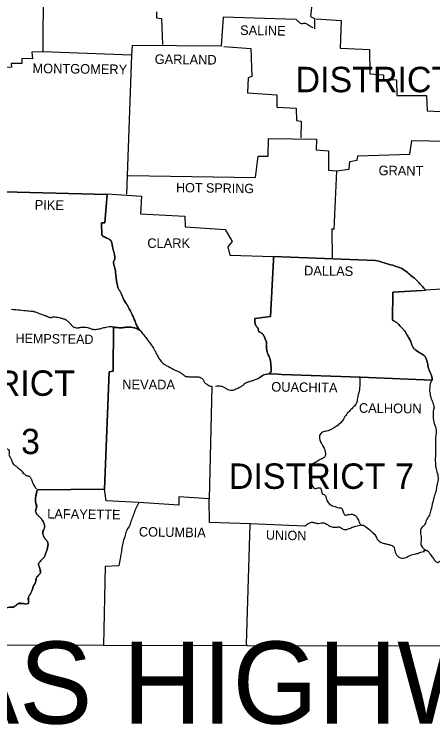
# Model space of a CAD drawing. Extents: x -43543 to 34500, y -13675 to 11152.
# Drawn here: x 11720 to 13557, y 4715 to 7833 of the extents above; entities that cross this region are included whole.
import ezdxf

# ---------------------------------------------------------------- set-up
doc = ezdxf.new("R2010")
doc.units = 0
for name, color, linetype in [('1', 7, 'Continuous'), ('2', 7, 'Continuous'), ('3', 7, 'Continuous'), ('R_Annotation', 7, 'Continuous')]:
    doc.layers.add(name, color=color, linetype=linetype)

msp = doc.modelspace()

# ---------------------------------------------------------------- linework, layer by layer
at = {"layer": '1'}
for points in [[(12379.4, 8503.9), (12375.5, 8363), (12152.5, 8362), (12123.1, 8336.6), (12106.5, 8297.5), (12082, 8299.4), (12081, 8276.9), (12052.7, 8274), (12053.6, 8253.4), (11911.8, 8257.3), (11906.9, 8241.7), (11848.2, 8239.7), (11846.2, 7667.4), (11797.3, 7666.4), (11801.2, 7637), (11754.2, 7638), (11753.3, 7616.5), (11707.3, 7616.5), (11708.3, 7600.8), (11639.8, 7598.9), (11638.8, 7539.2), (11572.3, 7545.1), (11561.5, 7063.7)], [(13347.1, 7958.9), (13276.6, 7966.8), (13279.6, 7940.3), (13151.4, 7935.4), (13147.5, 7897.3), (13027.1, 7890.4), (13020.3, 7822), (13037.9, 7813.1), (13037.9, 7768.1)], [(12345.2, 7843.5), (12344.2, 7817.1), (12366.7, 7813.1), (12370.6, 7699.6)], [(12957.7, 7809.2), (12637.7, 7819), (12628.9, 7692.8), (12237.6, 7694.8), (12235.6, 7652.7)], [(13044.8, 7812.2), (13154.3, 7805.3), (13150.4, 7683), (13278.6, 7678.1), (13280.6, 7571.5), (13341.2, 7566.6), (13341.2, 7548), (13398, 7544.1), (13399.9, 7475.6), (13529.1, 7475.6), (13533, 7408.1), (13652.3, 7402.2), (13651.4, 7275)], [(12640.7, 7690.8), (12759.1, 7682), (12763, 7558.8), (12746.3, 7552.9), (12744.4, 7487.3), (12872.6, 7478.5), (12872.6, 7424.7), (12957.7, 7419.8), (12958.7, 7366), (12979.2, 7363.1), (12978.2, 7290.7)], [(12235.6, 7652.7), (11846.2, 7667.4)], [(12235.6, 7652.7), (12213.1, 7043.1)], [(12220, 7124.3), (12779.6, 7116.5), (12790.4, 7209.5), (12834.4, 7209.5), (12835.4, 7287.7), (13046.7, 7284.8), (13044.8, 7237.8), (13099.5, 7233.9), (13099.5, 7147.8), (13134.8, 7144.9)], [(13134.8, 7144.9), (13189.6, 7152.7), (13193.5, 7186), (13225.8, 7191.9), (13227.7, 7211.4), (13455.7, 7218.3), (13464.5, 7278), (13698.3, 7274)], [(13134.8, 7144.9), (13123, 6888.6), (13114.2, 6891.5), (13115.2, 6758.4)], [(12127.8, 7042.1), (12128, 7044.1)], [(12128, 7044.1), (12278.7, 7034.3), (12274.8, 6957), (12469.5, 6946.3), (12470.4, 6899.3), (12646.5, 6888.6), (12676.9, 6835.7), (12658.3, 6812.2), (12667.1, 6776), (12858.7, 6769)], [(13667, 6630.3), (13524.2, 6621.4)], [(12587.8, 6199.8), (12575.1, 5706.6)], [(12264.5, 5690.1), (12124.1, 5697.8), (12117.2, 5748.7)], [(12994.9, 5587.3), (12755, 5596.3)], [(11681.9, 5065.4), (12112.4, 5064.6)], [(12742, 5063.6), (15008.4, 5059.9)]]:
    msp.add_lwpolyline(points, dxfattribs=at)
for points in [[(13031.1, 7773), (13012.5, 7782.8), (12997.8, 7791.6), (12982.1, 7790.6), (12969.4, 7798.5), (12957.7, 7809.2)], [(11708.3, 6538.3), (11745.4, 6535.3), (11779.7, 6531.4), (11792.9, 6530.4), (11799.5, 6529.7), (11802.8, 6529.2), (11806.1, 6528.5), (11813.1, 6526.5), (11819.9, 6524), (11833.5, 6518.7), (11858, 6509.9), (11861.9, 6508.3), (11865.7, 6506.4), (11869.6, 6504.6), (11873.6, 6503.1), (11880.1, 6502.4), (11886.7, 6503.5), (11893.4, 6504.9), (11900, 6505), (11911.3, 6502.9), (11922.5, 6500.1), (11935.6, 6496.6), (11941.9, 6494.4), (11945, 6493), (11948, 6491.3), (11957.8, 6483.5), (11966.6, 6474.7), (11969.4, 6471.5), (11972, 6468.2), (11976.4, 6463.4), (11977.3, 6462.7), (11978.3, 6462), (11983.8, 6459), (11989.4, 6457.5), (11995.1, 6457), (12000.8, 6457.1), (12005.4, 6457.6), (12010.1, 6458.6), (12014.7, 6459.6), (12019.4, 6460), (12041.9, 6458.1), (12048.3, 6456.3), (12054.6, 6453.9), (12060.9, 6451.6), (12067.3, 6450.2), (12072.4, 6449.8), (12077.6, 6449.9), (12087.9, 6451.2), (12104.5, 6455.1), (12124.1, 6460), (12136.3, 6461.9), (12142.4, 6462.1), (12148.5, 6462), (12153.2, 6461.3), (12157.9, 6460.1)], [(12271.9, 6445.9), (12278.7, 6437.5), (12308, 6400.3), (12321.7, 6381.6), (12328.1, 6371.9), (12334.4, 6362.2), (12338.4, 6355.3), (12341.9, 6348.1), (12345.4, 6340.9), (12349.1, 6333.8), (12358.9, 6317.1), (12364.7, 6309.4), (12368, 6305.8), (12371.6, 6302.5), (12384, 6293.9), (12397.1, 6286.8), (12429.3, 6270.2), (12449.9, 6260.4), (12455.8, 6256.3), (12461.3, 6251.3), (12466.9, 6246.7), (12470, 6244.9), (12473.4, 6243.8), (12488.5, 6242.1), (12503.7, 6241.8), (12515, 6241.9), (12520.6, 6241.9), (12526.2, 6241.8), (12531.7, 6241), (12536.9, 6239.1), (12542, 6236.4), (12546.7, 6233), (12549.9, 6229), (12551.9, 6224.2), (12553.7, 6219.4), (12556.5, 6215.4), (12560.6, 6212), (12564.8, 6208.9), (12574.1, 6203.7), (12587.8, 6199.8)], [(12815.8, 6250.6), (12790.4, 6234), (12770.8, 6226.2), (12756.1, 6221.3), (12742.4, 6217.4), (12724.8, 6205.6), (12711.1, 6195.8), (12692.5, 6187), (12674.9, 6181.2), (12653.4, 6188), (12641.7, 6194.9), (12628.9, 6199.8), (12602.9, 6199.8)], [(12790.4, 6234), (12815.8, 6250.6), (12834.4, 6254.5)], [(13236, 6240), (13233.6, 6179.2), (13226.7, 6148.9), (13219.9, 6121.5), (13205.2, 6105.8), (13189.6, 6090.2), (13174.9, 6072.6), (13162.2, 6051), (13149.4, 6037.3), (13132.8, 6023.6), (13116.2, 6013.9), (13097.6, 6005), (13077, 6000.2), (13062.4, 5989.4), (13061.4, 5965.9), (13078, 5932.6), (13083.9, 5917), (13085.9, 5898.4), (13079, 5887.6), (13063.3, 5878.8), (13044.8, 5868.1), (13028.1, 5858.3), (13016.4, 5841.7), (13014.4, 5819.2), (13022.3, 5792.7), (13025.2, 5777.1), (13037.9, 5752.6), (13047.7, 5753.6), (13065.3, 5752.6), (13067.3, 5747.7), (13068.2, 5742.8), (13072.2, 5730.1), (13086.8, 5719.4), (13088.8, 5709.6), (13097.6, 5691), (13112.3, 5678.3), (13123, 5674.3), (13145.5, 5667.5), (13157.3, 5664.6), (13170, 5636.2), (13185.6, 5637.2), (13197.4, 5639.1), (13217, 5634.2), (13225.8, 5622.5), (13234.6, 5602.9), (13244.5, 5590.4), (13251, 5591.2)], [(13553.5, 6227.3), (13551.5, 6223.6), (13549.1, 6220), (13547, 6216.3), (13545.7, 6212.5), (13545, 6207.7), (13544.3, 6202.8), (13543.3, 6193), (13543, 6183.1), (13543.7, 6173.3), (13546.1, 6160), (13549.6, 6146.9), (13551.4, 6142), (13553.5, 6137.1), (13555.5, 6132.3), (13557.4, 6127.3), (13559.3, 6121.8), (13560.8, 6116.2), (13561.8, 6110.5), (13562.2, 6107.6), (13562.3, 6104.8), (13561.6, 6101.3), (13560.6, 6099.6), (13559.4, 6098)], [(13559.4, 6098), (13563.3, 6037.3), (13572.1, 6008), (13569.2, 5976.7), (13568.2, 5946.3), (13568.2, 5918.9), (13568.2, 5892.5), (13568.2, 5865.1), (13570.2, 5845.6), (13577, 5817.2), (13579.9, 5790.8), (13574.1, 5765.3), (13571.1, 5741.9), (13563.3, 5718.4), (13556.5, 5692), (13548.6, 5657.7), (13541.8, 5635.2), (13528.1, 5611.7), (13519.3, 5590.2), (13505.6, 5576.5), (13503.6, 5553), (13506.6, 5531.5), (13504.6, 5511.9), (13511.5, 5493.3), (13529.1, 5480.6)], [(11663.2, 5926.8), (11666.4, 5928), (11669.6, 5930.3), (11672.8, 5932.2), (11676, 5932.6), (11681.3, 5930.7), (11686.7, 5927.8), (11692, 5924.8), (11694.3, 5923), (11695.5, 5922), (11696.5, 5920.9), (11698.7, 5915.1), (11698.2, 5908.4), (11697.3, 5901.6), (11698.5, 5895.5), (11700.4, 5892), (11702.4, 5888.6), (11704.4, 5885.2), (11706.3, 5881.8), (11709, 5875.5), (11711.3, 5869), (11715.9, 5859.9), (11716.9, 5858.6), (11718, 5857.3), (11722, 5853.8), (11726.2, 5850.7), (11730.5, 5847.7), (11734.7, 5844.6), (11742.6, 5838.3), (11750.3, 5831.9), (11752, 5830.1), (11753.4, 5828.1), (11754.7, 5826), (11756.2, 5824), (11764.1, 5816.2), (11768.4, 5812.7), (11772.8, 5809.4), (11776.4, 5807.9), (11780.3, 5807.2), (11784.2, 5806.4), (11786, 5805.7), (11787.5, 5804.5), (11791.4, 5799.4), (11794.4, 5793.7), (11797.1, 5787.4), (11799.7, 5781), (11802.3, 5774.6), (11805.1, 5768.3), (11810.2, 5759.2), (11813.4, 5755), (11815.2, 5752.9), (11817.3, 5750.8)], [(12994.9, 5587.3), (13010.5, 5598), (13025.2, 5603.9), (13039.9, 5601), (13055.5, 5599), (13069.2, 5601), (13086.8, 5598), (13101.5, 5589.2), (13118.1, 5582.4), (13134.8, 5582.4), (13149.4, 5582.4), (13162.2, 5573.6), (13185.6, 5574.5), (13205.2, 5582.4), (13224.8, 5588.2), (13251.2, 5591.2), (13274.7, 5574.5), (13291.3, 5560.9), (13305, 5545.2), (13314.8, 5527.6), (13325.6, 5517.8), (13343.2, 5511), (13356.9, 5508), (13373.5, 5503.1), (13382.3, 5499.2), (13390.1, 5480.6), (13402.9, 5455.2), (13427.3, 5446.4), (13457.6, 5458.1), (13482.1, 5465), (13499.7, 5470.8), (13510.5, 5474.8), (13520.3, 5475.7), (13517.3, 5477.7), (13529.1, 5480.6), (13539.8, 5472.8), (13546.7, 5462), (13558.4, 5446.4), (13569.2, 5432.7), (13579.9, 5427.8), (13590.7, 5433.7), (13605.4, 5428.8), (13618.1, 5423.9), (13632.8, 5420), (13645.5, 5419), (13662.1, 5415.1), (13674.9, 5408.2), (13686.6, 5401.4), (13698.3, 5388.7), (13710.1, 5369.1), (13714, 5353.4), (13727.7, 5337.8), (13740.4, 5337.8), (13759, 5312.3), (13765.8, 5302.6), (13780.5, 5284.9), (13791.3, 5284.9), (13808.2, 5281.7)]]:
    msp.add_spline(points, degree=3, dxfattribs=at)
at = {"layer": 'R_Annotation'}
for p, q in [((13305, 6752.6), (12858.7, 6769)), ((12270.7, 6445.9), (12271.9, 6445.9))]:
    msp.add_line(p, q, dxfattribs=at)
for points in [[(11561.5, 7056.9), (12127.8, 7042), (12127.8, 7042.1), (12118.2, 6917.9), (12102.6, 6916.9), (12104.5, 6863.1)], [(12104.5, 6863.1), (12102.6, 6916.9), (12118.2, 6917.9), (12127.8, 7042), (11561.5, 7056.9)], [(12776.7, 6498.2), (12844.2, 6506), (12858.7, 6754.1), (12858.7, 6769)], [(12858.7, 6769), (12858.7, 6754.1), (12844.2, 6506), (12776.7, 6498.2)], [(12858.7, 6769), (13305, 6752.6)], [(13380.4, 6490.3), (13381.3, 6612.6), (13508.7, 6620.5), (13525.8, 6621.5)], [(13508.7, 6620.5), (13381.3, 6612.6), (13380.4, 6490.3)], [(12156.4, 6460.4), (12154.4, 6266.3), (12136.8, 6264.3), (12117.2, 5748.7), (11820.8, 5745.8)], [(11820.8, 5745.8), (12117.2, 5748.7), (12136.8, 6264.3), (12154.4, 6266.3), (12156.4, 6460.4)], [(12270.7, 6445.9), (12271.4, 6446.5)], [(13553.5, 6227.6), (13239.5, 6239.9), (12893.3, 6252.4), (12880.5, 6252.9), (12834.4, 6254.5)], [(12839.1, 6254.4), (12880.5, 6252.9), (12893.3, 6252.4), (13239.5, 6239.9), (13553.5, 6227.3)], [(12755, 5596.3), (12577.1, 5602.9), (12575.1, 5701.7), (12575.1, 5706.6), (12443, 5715.4), (12442.1, 5679.2), (12267.7, 5689.9)], [(12755, 5596.3), (12577.1, 5602.9), (12575.1, 5701.7), (12575.1, 5706.6), (12443, 5715.4), (12442.1, 5679.2), (12267.8, 5689.9)], [(12179.8, 5413.1), (12119.2, 5409.2), (12112.3, 5064.6), (12112.4, 5064.6), (12742, 5063.6), (12739.9, 5069.7), (12755.1, 5594.1), (12755, 5596.3)], [(12179.8, 5413.1), (12119.2, 5409.2), (12112.3, 5064.6), (12742, 5063.6), (12739.9, 5069.7), (12755.1, 5594.1), (12755, 5596.3)]]:
    msp.add_lwpolyline(points, dxfattribs=at)
for points in [[(12104.5, 6863.1), (12120.2, 6853.3), (12124.7, 6851), (12129.4, 6849.1), (12134.2, 6847.1), (12138.8, 6844.5), (12145, 6838), (12148.5, 6829.8), (12149.7, 6824.2), (12150.5, 6818.6), (12151.4, 6812.9), (12152.5, 6807.3), (12154.1, 6801.2), (12155.9, 6795.1), (12157.7, 6789), (12159.3, 6782.9), (12160.5, 6776.6), (12161.1, 6770.1), (12161.4, 6763.7), (12161.3, 6757.4), (12160.2, 6753.9), (12158, 6750.6), (12156, 6747.2), (12155.4, 6743.7), (12157, 6736), (12159.2, 6728.2), (12161.6, 6720.4), (12163.2, 6712.4), (12166.1, 6690.9), (12169.1, 6665.5), (12172, 6648.1), (12174.1, 6639.6), (12176.9, 6631.2), (12179.7, 6625.1), (12183.1, 6619.3), (12186.5, 6613.6), (12189.6, 6607.7), (12192.6, 6600.7), (12195.3, 6593.5), (12198.1, 6586.3), (12201.4, 6579.4), (12206, 6571.6), (12211.1, 6564.2), (12216.3, 6556.8), (12220.9, 6549), (12237.6, 6515.8), (12245.4, 6498.2), (12248.9, 6489), (12252.1, 6479.8), (12255.6, 6470.7), (12260.1, 6462), (12265.8, 6453.7), (12271.9, 6445.9)], [(12170.5, 6656.2), (12169.1, 6665.5), (12166.1, 6690.9), (12163.2, 6712.4), (12161.6, 6720.4), (12159.2, 6728.2), (12157, 6736), (12155.4, 6743.7), (12156, 6747.2), (12158, 6750.6), (12160.2, 6753.9), (12161.3, 6757.4), (12161.4, 6763.7), (12161.1, 6770.1), (12160.5, 6776.6), (12159.3, 6782.9), (12157.7, 6789), (12155.9, 6795.1), (12154.1, 6801.2), (12152.5, 6807.3), (12151.4, 6812.9), (12150.5, 6818.6), (12149.7, 6824.2), (12148.5, 6829.8), (12145, 6838), (12138.8, 6844.5), (12134.2, 6847.1), (12129.4, 6849.1), (12124.7, 6851), (12120.2, 6853.3), (12104.5, 6863.1)], [(13305, 6752.6), (13381.3, 6731), (13420.5, 6716.4), (13459.6, 6688), (13491.9, 6659.6), (13525.8, 6621.5)], [(13525.8, 6621.5), (13491.9, 6659.6), (13459.6, 6688), (13420.5, 6716.4), (13381.3, 6731), (13305, 6752.6)], [(12271.4, 6446.5), (12265.8, 6453.7), (12260.1, 6462), (12255.6, 6470.7), (12252.1, 6479.8), (12248.9, 6489), (12245.4, 6498.2), (12237.6, 6515.8), (12220.9, 6549), (12216.3, 6556.8), (12211.1, 6564.2), (12206, 6571.6), (12201.4, 6579.4), (12198.1, 6586.3), (12195.3, 6593.5), (12192.6, 6600.7), (12189.6, 6607.7), (12186.5, 6613.6), (12183.1, 6619.3), (12179.7, 6625.1), (12176.9, 6631.2), (12174.1, 6639.6), (12172, 6648.1), (12170.5, 6656.2)], [(12776.7, 6498.2), (12776.7, 6479.6), (12779.4, 6470.6), (12781.3, 6466.2), (12783.5, 6462), (12785.1, 6459.8), (12786.9, 6458), (12788.8, 6456.1), (12790.4, 6454.1), (12791.3, 6451.1), (12791.5, 6447.6), (12791.8, 6444.2), (12793.3, 6441.4), (12794.3, 6440.5), (12795.4, 6439.8), (12797.6, 6438.4), (12799.9, 6437.1), (12802.1, 6435.5), (12803.8, 6434.2), (12805.6, 6432.9), (12809.1, 6430.3), (12814.8, 6423.8), (12821.7, 6407.2), (12822.9, 6404.5), (12824.3, 6401.9), (12825.6, 6399.2), (12826.6, 6396.4), (12826.8, 6395.6), (12826.9, 6394.7), (12826.9, 6389.6), (12826.6, 6386.1), (12826.6, 6382.7), (12827.6, 6369), (12828.3, 6360.7), (12829.5, 6352.4), (12830.5, 6348.6), (12831.8, 6344.8), (12835.1, 6337.6), (12838.5, 6330.4), (12841.2, 6323), (12844.2, 6311.3), (12846.1, 6301.5), (12846.8, 6293.2), (12847.1, 6284.9), (12847.3, 6280), (12847.4, 6275.1), (12847.3, 6270.2), (12847.1, 6265.3), (12846.3, 6262.5), (12844.3, 6259.5), (12839.1, 6254.4)], [(12834.4, 6254.5), (12847.1, 6265.3), (12847.1, 6284.9), (12846.1, 6301.5), (12844.2, 6311.3), (12841.2, 6323), (12829.5, 6352.4), (12827.6, 6369), (12826.6, 6382.7), (12826.6, 6396.4), (12821.7, 6407.2), (12814.8, 6423.8), (12802.1, 6435.5), (12793.3, 6441.4), (12790.4, 6454.1), (12783.5, 6462), (12776.7, 6479.6), (12776.7, 6498.2)], [(13380.4, 6490.3), (13386.6, 6487.3), (13392.4, 6483.9), (13397.9, 6480.1), (13402.9, 6475.7), (13421.4, 6456.1), (13428.4, 6448.8), (13431.8, 6445.2), (13433.5, 6443.3), (13435.1, 6441.4), (13437.8, 6437.6), (13439.9, 6433.3), (13441.8, 6429), (13443.9, 6424.8), (13449.8, 6415), (13455.7, 6405.2), (13460, 6396.1), (13463.5, 6386.5), (13467.3, 6377), (13469.6, 6372.4), (13470.9, 6370.2), (13472.3, 6368), (13479.1, 6361), (13487, 6355.3), (13507.5, 6342.6), (13514, 6338.5), (13517.2, 6336.3), (13518.8, 6335.1), (13520.3, 6333.8), (13525.2, 6327.7), (13528.6, 6320.6), (13531, 6313.1), (13533, 6305.4), (13534.6, 6298.3), (13535.8, 6291.1), (13537, 6284), (13538.9, 6277), (13541.3, 6270.6), (13544.1, 6264.3), (13547, 6258), (13549.6, 6251.6), (13552.8, 6241.8), (13553.9, 6236.9), (13554.3, 6234.5), (13554.5, 6232), (13553.5, 6227.3)], [(13477.6, 6362.2), (13472.3, 6368), (13470.9, 6370.2), (13469.6, 6372.4), (13467.3, 6377), (13463.5, 6386.5), (13460, 6396.1), (13455.7, 6405.2), (13449.8, 6415), (13443.9, 6424.8), (13441.8, 6429), (13439.9, 6433.3), (13437.8, 6437.6), (13435.1, 6441.4), (13433.5, 6443.3), (13431.8, 6445.2), (13428.4, 6448.8), (13421.4, 6456.1), (13402.9, 6475.7), (13397.9, 6480.1), (13392.4, 6483.9), (13386.6, 6487.3), (13380.4, 6490.3)], [(12270.7, 6445.9), (12267.8, 6448), (12264.9, 6449.9), (12258.8, 6453.1), (12246.1, 6457.4), (12220, 6460), (12212.9, 6459.5), (12205.8, 6458.5), (12198.7, 6457.5), (12191.6, 6457.1), (12179.4, 6457.3), (12167.1, 6458.1), (12162.5, 6458.9), (12156.4, 6460.4)], [(12156.4, 6460.4), (12162.5, 6458.9), (12167.1, 6458.1), (12179.4, 6457.3), (12191.6, 6457.1), (12198.7, 6457.5), (12205.8, 6458.5), (12212.9, 6459.5), (12220, 6460), (12246.1, 6457.4), (12258.8, 6453.1), (12264.9, 6449.9), (12267.8, 6448), (12270.7, 6445.9)], [(13553.5, 6227.3), (13554.5, 6232), (13554.3, 6234.5), (13553.9, 6236.9), (13552.8, 6241.8), (13549.6, 6251.6), (13547, 6258), (13544.1, 6264.3), (13541.3, 6270.6), (13538.9, 6277), (13537, 6284), (13535.8, 6291.1), (13534.6, 6298.3), (13533, 6305.4), (13531, 6313.1), (13528.6, 6320.6), (13525.2, 6327.7), (13520.3, 6333.8), (13518.8, 6335.1), (13517.2, 6336.3), (13514, 6338.5), (13507.5, 6342.6), (13487, 6355.3), (13479.1, 6361), (13477.6, 6362.2)], [(11820.8, 5745.8), (11814.9, 5717.4), (11813.9, 5694.9), (11818.8, 5668.5), (11813.9, 5655.8), (11821.7, 5637.2), (11836.4, 5622.5), (11847.2, 5606.8), (11854, 5584.3), (11845.2, 5558.9), (11855, 5532.5), (11863.8, 5522.7), (11868.7, 5507), (11861.9, 5476.7), (11853.1, 5454.2), (11833.5, 5431.7), (11827.6, 5420.9), (11830.6, 5406.3), (11835.4, 5382.8), (11830.6, 5375.9), (11817.8, 5359.3), (11813.9, 5340.7), (11805.1, 5325.1), (11795.3, 5296.7), (11782.6, 5273.2), (11780.7, 5246.8), (11761.1, 5246.8), (11738.6, 5246.8), (11718, 5232.1), (11699.4, 5231.1), (11676.9, 5222.3), (11663.2, 5203.7), (11658.4, 5183.2), (11652.5, 5163.6), (11658.4, 5130.4), (11667.2, 5106.9), (11674, 5088.3), (11680.9, 5070.4)], [(11827.9, 5372.4), (11830.6, 5375.9), (11833.7, 5379.2), (11835.4, 5382.8), (11835.4, 5383.5), (11835.4, 5384.2), (11835.2, 5385.7), (11834.8, 5388.6), (11833.5, 5394.5), (11832, 5400.4), (11830.6, 5406.3), (11827.6, 5420.9), (11833.5, 5431.7), (11838.4, 5437.5), (11843.7, 5442.8), (11848.8, 5448.1), (11853.1, 5454.2), (11858, 5465.2), (11861.9, 5476.7), (11866.2, 5491.9), (11867.8, 5499.5), (11868.7, 5507), (11863.8, 5522.7), (11861.8, 5525.4), (11859.5, 5527.6), (11857.1, 5529.8), (11855, 5532.5), (11848.6, 5545.6), (11846.5, 5552.3), (11845.2, 5558.9), (11846.3, 5565.3), (11849.6, 5571.6), (11852.9, 5578), (11854, 5584.3), (11853.2, 5589.9), (11851.8, 5595.6), (11849.8, 5601.2), (11847.2, 5606.8), (11842.1, 5615.1), (11836.4, 5622.5), (11832.9, 5626.2), (11829.2, 5629.5), (11825.3, 5633), (11821.7, 5637.2), (11816.5, 5646.4), (11814.8, 5651.1), (11813.9, 5655.8), (11814.5, 5658.9), (11816.3, 5662.1), (11818.1, 5665.3), (11818.8, 5668.5), (11817.8, 5675), (11816.2, 5681.6), (11814.6, 5688.2), (11813.9, 5694.9), (11814.9, 5717.4), (11816, 5725.2), (11817.4, 5733.2), (11820.8, 5745.8)], [(12267.8, 5689.9), (12250.3, 5654.8), (12241.5, 5630.3), (12232.7, 5606.8), (12225.8, 5587.3), (12215.1, 5570.6), (12207.2, 5547.2), (12198.4, 5518.8), (12192.6, 5492.4), (12189.6, 5468.9), (12184.7, 5444.4), (12179.8, 5413.1)], [(12267.8, 5689.9), (12250.3, 5654.8), (12241.5, 5630.3), (12232.7, 5606.8), (12225.8, 5587.3), (12215.1, 5570.6), (12207.2, 5547.2), (12198.4, 5518.8), (12192.6, 5492.4), (12189.6, 5468.9), (12184.7, 5444.4), (12179.8, 5413.1)], [(11680.9, 5070.4), (11674, 5088.3), (11667.2, 5106.9), (11658.4, 5130.4), (11655.5, 5138.5), (11653.2, 5146.9), (11652, 5155.3), (11652.5, 5163.6), (11655.2, 5173.4), (11656.9, 5178.3), (11658.4, 5183.2), (11663.2, 5203.7), (11668.4, 5213.9), (11672.3, 5218.4), (11676.9, 5222.3), (11687.9, 5228), (11699.4, 5231.1), (11704.1, 5231.7), (11708.8, 5231.6), (11713.5, 5231.5), (11718, 5232.1), (11723.4, 5235.2), (11728.2, 5240.2), (11732.9, 5244.8), (11738.6, 5246.8), (11761.1, 5246.8), (11780.7, 5246.8), (11783.1, 5247.6), (11784.2, 5249.8), (11783.6, 5257.1), (11782, 5265.8), (11782.6, 5273.2), (11785.7, 5279), (11789.1, 5284.8), (11792.5, 5290.7), (11795.3, 5296.7), (11797.9, 5303.7), (11800.2, 5310.9), (11802.5, 5318), (11805.1, 5325.1), (11807.1, 5329.1), (11809.5, 5332.9), (11811.8, 5336.8), (11813.9, 5340.7), (11815.1, 5345.3), (11815.5, 5350.2), (11816.1, 5355), (11817.8, 5359.3), (11827.9, 5372.4)]]:
    msp.add_spline(points, degree=3, dxfattribs=at)

# ---------------------------------------------------------------- texts
at = {"layer": '2'}
for s, height, rotation, p in [('SALINE', 42.07, 359.1491, (12711.1, 7741.7)), ('GARLAND', 42.07, 359.3658, (12336.4, 7614.5)), ('MONTGOMERY', 42.07, 359.2944, (11800.2, 7574.4)), ('GRANT', 42.07, 359.4032, (13318.7, 7126.3)), ('HOT SPRING', 41.09, 359.2216, (12430.3, 7051.9)), ('PIKE', 42.06, 359.0452, (11810, 6975.6)), ('DALLAS', 42.06, 359.2462, (12991.9, 6687)), ('HEMPSTEAD', 41.08, 359.1885, (11725.9, 6390.5)), ('OUACHITA', 42.07, 359.2043, (12848.1, 6177.2)), ('CALHOUN', 42.07, 359.3634, (13232.6, 6084.3)), ('LAFAYETTE', 42.06, 359.1839, (11864.8, 5620.5)), ('COLUMBIA', 42.06, 359.2125, (12266.9, 5541.3)), ('UNION', 41.09, 358.9584, (12824.6, 5527.6))]:
    msp.add_text(s, height=height, rotation=rotation, dxfattribs=at).set_placement(p)
for s, height, p in [('CLARK', 42.07, (12304.3, 6807.1)), ('NEVADA', 42.07, (12194.5, 6187)), ('ARKANSAS HIGHWAY DISTRICTS 3 & 7', 360, (9441.3, 4720.5))]:
    msp.add_text(s, height=height, dxfattribs=at).set_placement(p)
at = {"layer": '3'}
for s, height, p in [('DISTRICT 6', 111.54, (12954.7, 7490.3)), ('DISTRICT', 111.54, (11299.6, 6158.4)), ('3', 110.6, (11750.6, 5903.1)), ('DISTRICT 7', 111.54, (12662, 5750.3))]:
    msp.add_text(s, height=height, dxfattribs=at).set_placement(p)

doc.saveas('drawing.dxf')
